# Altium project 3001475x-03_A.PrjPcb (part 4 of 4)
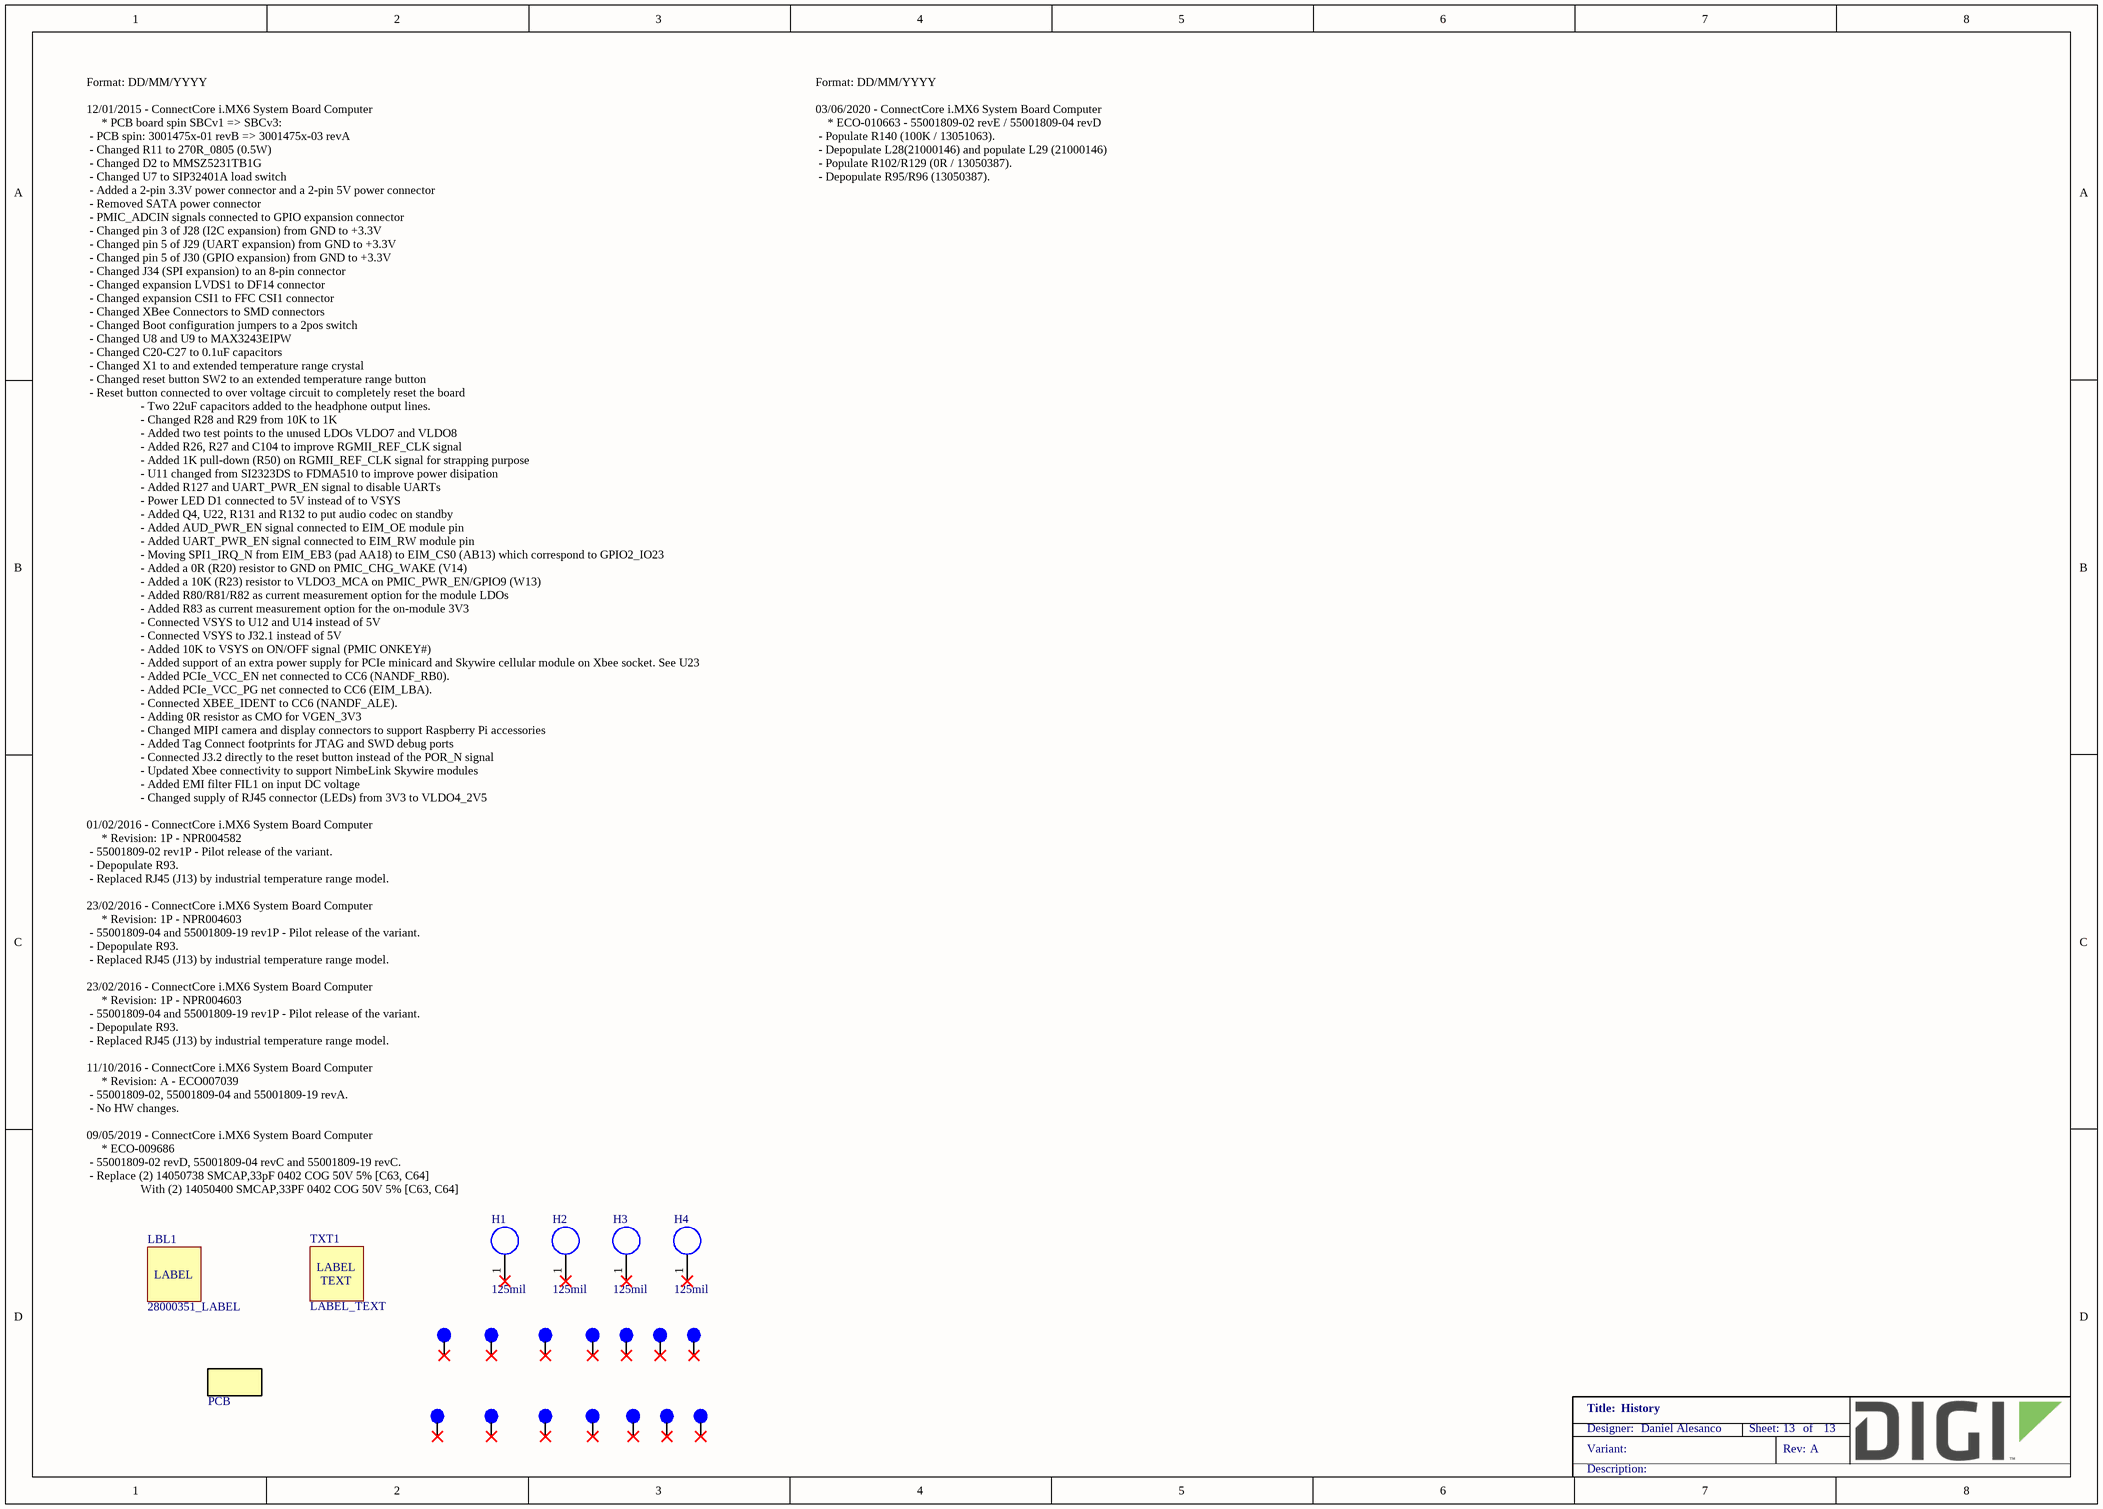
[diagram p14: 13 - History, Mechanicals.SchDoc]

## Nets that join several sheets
3V3: 02 - CCIMX6 Module (R83.1 U1.P5 U1.Y9 U1.Y13), 03 - Power, boot strap, reset (14 pins), 04 - SATA, microSD, Mini PCIe, microSIM (9 pins), 05 - JTAG, SWD, Console, UART (13 pins), 06 - Gigabit Ethernet (L2.1 U11.4 U11.8), 07 - USB OTG, USB HUB, USB Host (8 pins), 08 - Displays, HDMI, Cameras (19 pins), 09 - Audio (R93.2 R128.1 R132.2 U22.S), 10 - CAN, I2C, XBee (8 pins), 11 - Expansion Connectors, User LEDs (6 pins)
5V: 02 - CCIMX6 Module (U1.F16), 03 - Power, boot strap, reset (J5.1 R12.2 R21.2), 08 - Displays, HDMI, Cameras (7 pins)
GND: 02 - CCIMX6 Module (61 pins), 03 - Power, boot strap, reset (37 pins), 04 - SATA, microSD, Mini PCIe, microSIM (52 pins), 05 - JTAG, SWD, Console, UART (17 pins), 06 - Gigabit Ethernet (38 pins), 07 - USB OTG, USB HUB, USB Host (38 pins), 08 - Displays, HDMI, Cameras (53 pins), 09 - Audio (12 pins), 10 - CAN, I2C, XBee (15 pins), 11 - Expansion Connectors, User LEDs (12 pins)
PCIe_VCC: 04 - SATA, microSD, Mini PCIe, microSIM (18 pins), 10 - CAN, I2C, XBee (L29.1)
SHLD: 04 - SATA, microSD, Mini PCIe, microSIM (J7.11 J7.12), 06 - Gigabit Ethernet (C33.1 J13.SHLD1 J13.SHLD2 R46.2), 07 - USB OTG, USB HUB, USB Host (8 pins), 08 - Displays, HDMI, Cameras (P1.M1 P1.M2 P1.M3 P1.M4)
VCC_LICELL: 02 - CCIMX6 Module (U1.N3), 03 - Power, boot strap, reset (R8.2)
VLDO3_MCA: 02 - CCIMX6 Module (R23.2 R80.1 R153.2 U1.AC10), 05 - JTAG, SWD, Console, UART (CAD2.1 J11.1 R150.1)
VLDO4_2V5: 02 - CCIMX6 Module (R81.1 U1.R5 U1.V3), 06 - Gigabit Ethernet (14 pins)
VLDO6_1V5: 02 - CCIMX6 Module (R82.1), 04 - SATA, microSD, Mini PCIe, microSIM (5 pins), 09 - Audio (R131.2)
VSYS: 02 - CCIMX6 Module (U1.V11 U1.W11 U1.W12), 03 - Power, boot strap, reset (8 pins), 04 - SATA, microSD, Mini PCIe, microSIM (7 pins), 05 - JTAG, SWD, Console, UART (R151.1 R152.1), 07 - USB OTG, USB HUB, USB Host (C62.2 C65.1 U12.7 U14.7), 08 - Displays, HDMI, Cameras (J18.1), 10 - CAN, I2C, XBee (R101.1), 11 - Expansion Connectors, User LEDs (J32.1)
AUD_CLK: 02 - CCIMX6 Module (R1.2), 09 - Audio (U17.21)
AUD_HP_DET: 02 - CCIMX6 Module (U1.J24), 09 - Audio (D9.2 J22.5 R93.1)
AUD_I2C_SCL: 09 - Audio (U17.29), 10 - CAN, I2C, XBee (R114.2)
AUD_I2C_SDA: 09 - Audio (U17.27), 10 - CAN, I2C, XBee (R115.2)
AUD_PWR_EN: 02 - CCIMX6 Module (U1.V15), 09 - Audio (Q4.G R132.1)
AUD_RXD: 02 - CCIMX6 Module (U1.M5), 09 - Audio (U17.25)
AUD_TXC: 02 - CCIMX6 Module (U1.B7), 09 - Audio (U17.24)
AUD_TXD: 02 - CCIMX6 Module (U1.C7), 09 - Audio (U17.26)
AUD_TXFS: 02 - CCIMX6 Module (U1.C5), 09 - Audio (U17.23)
BOOT_CFG_1_4: 02 - CCIMX6 Module (U1.W24), 03 - Power, boot strap, reset (R18.1)
BOOT_CFG_1_5: 02 - CCIMX6 Module (U1.AA19), 03 - Power, boot strap, reset (R10.1 SW3.3 U4.1)
BOOT_CFG_1_6: 02 - CCIMX6 Module (U1.U23), 03 - Power, boot strap, reset (R9.1 SW3.4 U2.1)
BOOT_CFG_1_7: 02 - CCIMX6 Module (U1.Y21), 03 - Power, boot strap, reset (R19.1)
BOOT_CFG_2_5: 02 - CCIMX6 Module (U1.V20), 03 - Power, boot strap, reset (R16.1)
BOOT_CFG_2_6: 02 - CCIMX6 Module (U1.W21), 03 - Power, boot strap, reset (R17.1)
BOOT_MODE0: 02 - CCIMX6 Module (U1.E17), 03 - Power, boot strap, reset (R24.1 R28.1)
BOOT_MODE1: 02 - CCIMX6 Module (U1.F15), 03 - Power, boot strap, reset (R25.1 R29.1)
CAN1_H: 10 - CAN, I2C, XBee (R104.2 U18.7), 11 - Expansion Connectors, User LEDs (J27.2)
CAN1_L: 10 - CAN, I2C, XBee (R104.1 U18.6), 11 - Expansion Connectors, User LEDs (J27.1)
CAN1_RXD: 02 - CCIMX6 Module (U1.F3), 10 - CAN, I2C, XBee (U18.4)
CAN1_STBY: 02 - CCIMX6 Module (U1.G3), 10 - CAN, I2C, XBee (U18.8)
CAN1_TXD: 02 - CCIMX6 Module (U1.P3), 10 - CAN, I2C, XBee (U18.1)
CAN2_H: 10 - CAN, I2C, XBee (R116.2 U19.7), 11 - Expansion Connectors, User LEDs (J27.5)
CAN2_L: 10 - CAN, I2C, XBee (R116.1 U19.6), 11 - Expansion Connectors, User LEDs (J27.4)
CAN2_RXD: 02 - CCIMX6 Module (U1.D21), 10 - CAN, I2C, XBee (U19.4)
CAN2_STBY: 02 - CCIMX6 Module (U1.R3), 10 - CAN, I2C, XBee (U19.8)
CAN2_TXD: 02 - CCIMX6 Module (U1.F20), 10 - CAN, I2C, XBee (U19.1)
CLK1_N: 02 - CCIMX6 Module (U1.B18), 04 - SATA, microSD, Mini PCIe, microSIM (C31.1)
CLK1_P: 02 - CCIMX6 Module (U1.A18), 04 - SATA, microSD, Mini PCIe, microSIM (C32.1)
CSI0_DAT12: 02 - CCIMX6 Module (U1.L5), 08 - Displays, HDMI, Cameras (J17.2)
CSI0_DAT13: 02 - CCIMX6 Module (U1.C6), 08 - Displays, HDMI, Cameras (J17.3)
CSI0_DAT14: 02 - CCIMX6 Module (U1.B6), 08 - Displays, HDMI, Cameras (J17.4)
CSI0_DAT15: 02 - CCIMX6 Module (U1.E6), 08 - Displays, HDMI, Cameras (J17.5)
CSI0_DAT16: 02 - CCIMX6 Module (U1.H6), 08 - Displays, HDMI, Cameras (J17.6)
CSI0_DAT17: 02 - CCIMX6 Module (U1.A7), 08 - Displays, HDMI, Cameras (J17.7)
CSI0_DAT18: 02 - CCIMX6 Module (U1.F6), 08 - Displays, HDMI, Cameras (J17.8)
CSI0_DAT19: 02 - CCIMX6 Module (U1.G6), 08 - Displays, HDMI, Cameras (J17.9)
CSI0_GPIO: 02 - CCIMX6 Module (U1.E5), 08 - Displays, HDMI, Cameras (J17.15)
CSI0_HSYNC: 02 - CCIMX6 Module (U1.A5), 08 - Displays, HDMI, Cameras (J17.13)
CSI0_I2C_SCL: 08 - Displays, HDMI, Cameras (J17.18), 10 - CAN, I2C, XBee (R108.2)
CSI0_I2C_SDA: 08 - Displays, HDMI, Cameras (J17.19), 10 - CAN, I2C, XBee (R111.2)
CSI0_MCLK: 02 - CCIMX6 Module (R3.2), 08 - Displays, HDMI, Cameras (J17.11)
CSI0_PIXCLK: 02 - CCIMX6 Module (U1.G5), 08 - Displays, HDMI, Cameras (J17.12)
CSI0_RESET_N: 02 - CCIMX6 Module (U1.AA13), 08 - Displays, HDMI, Cameras (J17.16)
CSI0_VSYNC: 02 - CCIMX6 Module (U1.J5), 08 - Displays, HDMI, Cameras (J17.14)
CSI1_DAT12: 02 - CCIMX6 Module (U1.AC17), 08 - Displays, HDMI, Cameras (J33.2)
CSI1_DAT13: 02 - CCIMX6 Module (U1.AB15), 08 - Displays, HDMI, Cameras (J33.3)
CSI1_DAT14: 02 - CCIMX6 Module (U1.AD16), 08 - Displays, HDMI, Cameras (J33.4)
CSI1_DAT15: 02 - CCIMX6 Module (U1.AB16), 08 - Displays, HDMI, Cameras (J33.5)
CSI1_DAT16: 02 - CCIMX6 Module (U1.AC16), 08 - Displays, HDMI, Cameras (J33.6)
CSI1_DAT17: 02 - CCIMX6 Module (U1.AC19), 08 - Displays, HDMI, Cameras (J33.7)
CSI1_DAT18: 02 - CCIMX6 Module (U1.AA14), 08 - Displays, HDMI, Cameras (J33.8)
CSI1_DAT19: 02 - CCIMX6 Module (U1.AD17), 08 - Displays, HDMI, Cameras (J33.9)
CSI1_GPIO: 02 - CCIMX6 Module (U1.W18), 08 - Displays, HDMI, Cameras (J33.15)
CSI1_HSYNC: 03 - Power, boot strap, reset (U2.3), 08 - Displays, HDMI, Cameras (J33.13)
CSI1_HSYNC/BTCFG2_3: 02 - CCIMX6 Module (U1.V18), 03 - Power, boot strap, reset (U2.4)
CSI1_I2C_SCL: 08 - Displays, HDMI, Cameras (J33.18), 10 - CAN, I2C, XBee (R207.2)
CSI1_I2C_SDA: 08 - Displays, HDMI, Cameras (J33.19), 10 - CAN, I2C, XBee (R208.2)
CSI1_MCLK: 02 - CCIMX6 Module (R2.2), 08 - Displays, HDMI, Cameras (J33.11)
CSI1_PIXCLK: 02 - CCIMX6 Module (U1.AD15), 08 - Displays, HDMI, Cameras (J33.12)
CSI1_RESET_N: 02 - CCIMX6 Module (U1.Y20), 08 - Displays, HDMI, Cameras (J33.16)
CSI1_VSYNC: 03 - Power, boot strap, reset (U4.3), 08 - Displays, HDMI, Cameras (J33.14)
CSI1_VSYNC/BTCFG2_4: 02 - CCIMX6 Module (U1.V22), 03 - Power, boot strap, reset (U4.4)
CSI_CLK0_N: 02 - CCIMX6 Module (U1.B11), 08 - Displays, HDMI, Cameras (P20.8)
CSI_CLK0_P: 02 - CCIMX6 Module (U1.A11), 08 - Displays, HDMI, Cameras (P20.7)
CSI_D0_N: 02 - CCIMX6 Module (U1.G12), 08 - Displays, HDMI, Cameras (P20.14)
CSI_D0_P: 02 - CCIMX6 Module (U1.G11), 08 - Displays, HDMI, Cameras (P20.13)
CSI_D1_N: 02 - CCIMX6 Module (U1.A13), 08 - Displays, HDMI, Cameras (P20.11)
CSI_D1_P: 02 - CCIMX6 Module (U1.B13), 08 - Displays, HDMI, Cameras (P20.10)
CSI_I2C_SCL: 08 - Displays, HDMI, Cameras (P20.3), 10 - CAN, I2C, XBee (R112.2)
CSI_I2C_SDA: 08 - Displays, HDMI, Cameras (P20.2), 10 - CAN, I2C, XBee (R113.2)
CSI_RESET_N: 02 - CCIMX6 Module (U1.E24), 08 - Displays, HDMI, Cameras (P20.5)
DISP0_CLK: 02 - CCIMX6 Module (U1.V9), 08 - Displays, HDMI, Cameras (J21.27)
DISP0_CONTRAST: 02 - CCIMX6 Module (U1.AD8), 08 - Displays, HDMI, Cameras (J21.32)
DISP0_DAT0: 02 - CCIMX6 Module (U1.AC8), 08 - Displays, HDMI, Cameras (J21.2)
DISP0_DAT1: 02 - CCIMX6 Module (U1.AC9), 08 - Displays, HDMI, Cameras (J21.3)
DISP0_DAT2: 02 - CCIMX6 Module (U1.AD9), 08 - Displays, HDMI, Cameras (J21.4)
DISP0_DAT3: 02 - CCIMX6 Module (U1.AB8), 08 - Displays, HDMI, Cameras (J21.5)
DISP0_DAT4: 02 - CCIMX6 Module (U1.AA9), 08 - Displays, HDMI, Cameras (J21.6)
DISP0_DAT5: 02 - CCIMX6 Module (U1.AD7), 08 - Displays, HDMI, Cameras (J21.7)
DISP0_DAT6: 02 - CCIMX6 Module (U1.AB7), 08 - Displays, HDMI, Cameras (J21.8)
DISP0_DAT7: 02 - CCIMX6 Module (U1.AC7), 08 - Displays, HDMI, Cameras (J21.9)
DISP0_DAT8: 02 - CCIMX6 Module (U1.AA8), 08 - Displays, HDMI, Cameras (J21.10)
DISP0_DAT9: 02 - CCIMX6 Module (U1.AB6), 08 - Displays, HDMI, Cameras (J21.11)
DISP0_DAT10: 02 - CCIMX6 Module (U1.Y8), 08 - Displays, HDMI, Cameras (J21.12)
DISP0_DAT11: 02 - CCIMX6 Module (U1.Y7), 08 - Displays, HDMI, Cameras (J21.13)
DISP0_DAT12: 02 - CCIMX6 Module (U1.AA7), 08 - Displays, HDMI, Cameras (J21.14)
DISP0_DAT13: 02 - CCIMX6 Module (U1.W8), 08 - Displays, HDMI, Cameras (J21.15)
DISP0_DAT14: 02 - CCIMX6 Module (U1.AC6), 08 - Displays, HDMI, Cameras (J21.16)
DISP0_DAT15: 02 - CCIMX6 Module (U1.W7), 08 - Displays, HDMI, Cameras (J21.17)
DISP0_DAT16: 02 - CCIMX6 Module (U1.V6), 08 - Displays, HDMI, Cameras (J21.18)
DISP0_DAT17: 02 - CCIMX6 Module (U1.AB5), 08 - Displays, HDMI, Cameras (J21.19)
DISP0_DAT18: 02 - CCIMX6 Module (U1.AD6), 08 - Displays, HDMI, Cameras (J21.20)
DISP0_DAT19: 02 - CCIMX6 Module (U1.Y6), 08 - Displays, HDMI, Cameras (J21.21)
DISP0_DAT20: 02 - CCIMX6 Module (U1.W6), 08 - Displays, HDMI, Cameras (J21.22)
DISP0_DAT21: 02 - CCIMX6 Module (U1.U6), 08 - Displays, HDMI, Cameras (J21.23)
DISP0_DAT22: 02 - CCIMX6 Module (U1.V7), 08 - Displays, HDMI, Cameras (J21.24)
DISP0_DAT23: 02 - CCIMX6 Module (U1.AA6), 08 - Displays, HDMI, Cameras (J21.25)
DISP0_DRDY: 02 - CCIMX6 Module (U1.V10), 08 - Displays, HDMI, Cameras (J21.31)
DISP0_HSYNC: 02 - CCIMX6 Module (U1.W10), 08 - Displays, HDMI, Cameras (J21.29)
DISP0_I2C_SCL: 08 - Displays, HDMI, Cameras (J21.33), 10 - CAN, I2C, XBee (R103.2)
DISP0_I2C_SDA: 08 - Displays, HDMI, Cameras (J21.34), 10 - CAN, I2C, XBee (R105.2)
DISP0_IRQ_N: 02 - CCIMX6 Module (U1.H22), 08 - Displays, HDMI, Cameras (J21.35 R78.2)
DISP0_VSYNC: 02 - CCIMX6 Module (U1.V8), 08 - Displays, HDMI, Cameras (J21.30)
DSI_CLK0_N: 02 - CCIMX6 Module (U1.E10), 08 - Displays, HDMI, Cameras (P18.11)
DSI_CLK0_P: 02 - CCIMX6 Module (U1.F10), 08 - Displays, HDMI, Cameras (P18.10)
DSI_D0_N: 02 - CCIMX6 Module (U1.C10), 08 - Displays, HDMI, Cameras (P18.8)
DSI_D0_P: 02 - CCIMX6 Module (U1.B10), 08 - Displays, HDMI, Cameras (P18.7)
DSI_D1_N: 02 - CCIMX6 Module (U1.E9), 08 - Displays, HDMI, Cameras (P18.14)
DSI_D1_P: 02 - CCIMX6 Module (U1.D9), 08 - Displays, HDMI, Cameras (P18.13)
DSI_I2C_SCL: 08 - Displays, HDMI, Cameras (P18.5), 10 - CAN, I2C, XBee (R155.2)
DSI_I2C_SDA: 08 - Displays, HDMI, Cameras (P18.4), 10 - CAN, I2C, XBee (R156.2)
EXP_GPIO_0: 02 - CCIMX6 Module (U1.L24), 11 - Expansion Connectors, User LEDs (J30.6)
EXP_GPIO_1: 02 - CCIMX6 Module (U1.G22), 11 - Expansion Connectors, User LEDs (J30.7)
EXP_GPIO_2: 02 - CCIMX6 Module (U1.H23), 11 - Expansion Connectors, User LEDs (J30.8)
EXP_GPIO_3: 02 - CCIMX6 Module (U1.AC15), 11 - Expansion Connectors, User LEDs (J30.9)
EXP_GPIO_4: 02 - CCIMX6 Module (U1.Y14), 11 - Expansion Connectors, User LEDs (J30.10)
EXP_GPIO_5: 02 - CCIMX6 Module (U1.V16), 11 - Expansion Connectors, User LEDs (J30.11)
EXP_GPIO_6: 02 - CCIMX6 Module (U1.N2), 11 - Expansion Connectors, User LEDs (J30.12)
EXP_GPIO_7: 02 - CCIMX6 Module (U1.M2), 11 - Expansion Connectors, User LEDs (J30.13)
EXP_I2C_GPIO: 02 - CCIMX6 Module (U1.F23), 11 - Expansion Connectors, User LEDs (J28.5)
EXP_I2C_IRQ_N: 02 - CCIMX6 Module (U1.H24), 11 - Expansion Connectors, User LEDs (J28.4 R117.2)
EXP_I2C_SCL: 10 - CAN, I2C, XBee (R106.2), 11 - Expansion Connectors, User LEDs (J28.1)
EXP_I2C_SDA: 10 - CAN, I2C, XBee (R107.2), 11 - Expansion Connectors, User LEDs (J28.2)
HDMI_CEC_IN: 02 - CCIMX6 Module (U1.H2), 08 - Displays, HDMI, Cameras (R88.2 U16.16)
HDMI_CLK_N: 02 - CCIMX6 Module (U1.E8), 08 - Displays, HDMI, Cameras (L43.4)
HDMI_CLK_P: 02 - CCIMX6 Module (U1.F8), 08 - Displays, HDMI, Cameras (L43.1)
HDMI_D0_N: 02 - CCIMX6 Module (U1.A9), 08 - Displays, HDMI, Cameras (L41.4)
HDMI_D0_P: 02 - CCIMX6 Module (U1.B9), 08 - Displays, HDMI, Cameras (L41.1)
HDMI_D1_N: 02 - CCIMX6 Module (U1.B8), 08 - Displays, HDMI, Cameras (L39.4)
HDMI_D1_P: 02 - CCIMX6 Module (U1.C8), 08 - Displays, HDMI, Cameras (L39.1)
HDMI_D2_N: 02 - CCIMX6 Module (U1.F7), 08 - Displays, HDMI, Cameras (L37.4)
HDMI_D2_P: 02 - CCIMX6 Module (U1.G7), 08 - Displays, HDMI, Cameras (L37.1)
HDMI_HPD: 02 - CCIMX6 Module (U1.G9), 08 - Displays, HDMI, Cameras (C83.2 R90.2 U16.19)
HDMI_I2C_SCL: 08 - Displays, HDMI, Cameras (U16.17), 10 - CAN, I2C, XBee (R99.2)
HDMI_I2C_SDA: 08 - Displays, HDMI, Cameras (U16.18), 10 - CAN, I2C, XBee (R100.2)
I2C3_SCL: 02 - CCIMX6 Module (U1.T3), 10 - CAN, I2C, XBee (12 pins)
I2C3_SDA: 02 - CCIMX6 Module (U1.J3), 10 - CAN, I2C, XBee (12 pins)
JTAG_MOD: 02 - CCIMX6 Module (U1.G13), 05 - JTAG, SWD, Console, UART (R37.2)
JTAG_TCK: 02 - CCIMX6 Module (U1.F13), 05 - JTAG, SWD, Console, UART (CAD1.4 J10.4)
JTAG_TDI: 02 - CCIMX6 Module (U1.D14), 05 - JTAG, SWD, Console, UART (CAD1.8 J10.8)
JTAG_TDO: 02 - CCIMX6 Module (U1.E14), 05 - JTAG, SWD, Console, UART (CAD1.6 J10.6)
JTAG_TMS: 02 - CCIMX6 Module (U1.F14), 05 - JTAG, SWD, Console, UART (CAD1.2 J10.2)
JTAG_TRST_N: 02 - CCIMX6 Module (U1.D15), 05 - JTAG, SWD, Console, UART (CAD1.9 R36.1)
LINE_IN_L: 09 - Audio (L21.1), 11 - Expansion Connectors, User LEDs (J26.4)
LINE_IN_R: 09 - Audio (L20.1), 11 - Expansion Connectors, User LEDs (J26.3)
LINE_OUT_L: 09 - Audio (L19.2), 11 - Expansion Connectors, User LEDs (J26.7)
LINE_OUT_R: 09 - Audio (L18.2), 11 - Expansion Connectors, User LEDs (J26.6)
LVDS0_CLK_N: 02 - CCIMX6 Module (U1.M4), 08 - Displays, HDMI, Cameras (L33.1)
LVDS0_CLK_P: 02 - CCIMX6 Module (U1.L4), 08 - Displays, HDMI, Cameras (L33.4)
LVDS0_CONTRAST: 02 - CCIMX6 Module (U1.V12), 08 - Displays, HDMI, Cameras (J19.16)
LVDS0_I2C_SCL: 08 - Displays, HDMI, Cameras (J19.17), 10 - CAN, I2C, XBee (R97.2)
LVDS0_I2C_SDA: 08 - Displays, HDMI, Cameras (J19.18), 10 - CAN, I2C, XBee (R98.2)
LVDS0_IRQ_N: 02 - CCIMX6 Module (U1.M3), 08 - Displays, HDMI, Cameras (J19.19 R76.2)
LVDS0_TX0_N: 02 - CCIMX6 Module (U1.J4), 08 - Displays, HDMI, Cameras (L30.1)
LVDS0_TX0_P: 02 - CCIMX6 Module (U1.H4), 08 - Displays, HDMI, Cameras (L30.4)
LVDS0_TX1_N: 02 - CCIMX6 Module (U1.F4), 08 - Displays, HDMI, Cameras (L31.1)
LVDS0_TX1_P: 02 - CCIMX6 Module (U1.E4), 08 - Displays, HDMI, Cameras (L31.4)
LVDS0_TX2_N: 02 - CCIMX6 Module (U1.C4), 08 - Displays, HDMI, Cameras (L32.1)
LVDS0_TX2_P: 02 - CCIMX6 Module (U1.B4), 08 - Displays, HDMI, Cameras (L32.4)
LVDS0_TX3_N: 02 - CCIMX6 Module (U1.R4), 08 - Displays, HDMI, Cameras (L34.1)
LVDS0_TX3_P: 02 - CCIMX6 Module (U1.P4), 08 - Displays, HDMI, Cameras (L34.4)
LVDS1_CLK_N: 02 - CCIMX6 Module (U1.E1), 08 - Displays, HDMI, Cameras (L42.1)
LVDS1_CLK_P: 02 - CCIMX6 Module (U1.F1), 08 - Displays, HDMI, Cameras (L42.4)
LVDS1_CONTRAST: 02 - CCIMX6 Module (U1.V13), 08 - Displays, HDMI, Cameras (J31.16)
LVDS1_I2C_SCL: 08 - Displays, HDMI, Cameras (J31.17), 10 - CAN, I2C, XBee (R298.2)
LVDS1_I2C_SDA: 08 - Displays, HDMI, Cameras (J31.18), 10 - CAN, I2C, XBee (R299.2)
LVDS1_IRQ_N: 02 - CCIMX6 Module (U1.AC20), 08 - Displays, HDMI, Cameras (J31.19 R118.2)
LVDS1_TX0_N: 02 - CCIMX6 Module (U1.H1), 08 - Displays, HDMI, Cameras (L36.1)
LVDS1_TX0_P: 02 - CCIMX6 Module (U1.J1), 08 - Displays, HDMI, Cameras (L36.4)
LVDS1_TX1_N: 02 - CCIMX6 Module (U1.M1), 08 - Displays, HDMI, Cameras (L38.1)
LVDS1_TX1_P: 02 - CCIMX6 Module (U1.L1), 08 - Displays, HDMI, Cameras (L38.4)
LVDS1_TX2_N: 02 - CCIMX6 Module (U1.P1), 08 - Displays, HDMI, Cameras (L40.1)
LVDS1_TX2_P: 02 - CCIMX6 Module (U1.R1), 08 - Displays, HDMI, Cameras (L40.4)
LVDS1_TX3_N: 02 - CCIMX6 Module (U1.U1), 08 - Displays, HDMI, Cameras (L44.1)
LVDS1_TX3_P: 02 - CCIMX6 Module (U1.V1), 08 - Displays, HDMI, Cameras (L44.4)
MCA_RESET_N: 02 - CCIMX6 Module (U1.N23), 05 - JTAG, SWD, Console, UART (CAD2.10 J11.10)
MCA_SWD_CLK: 02 - CCIMX6 Module (U1.L23), 05 - JTAG, SWD, Console, UART (CAD2.4 J11.4)
MCA_SWD_DIO: 02 - CCIMX6 Module (U1.M23), 05 - JTAG, SWD, Console, UART (CAD2.2 J11.2)
MIC_BIAS: 09 - Audio (L23.1), 11 - Expansion Connectors, User LEDs (J26.1)
MIC_IN: 09 - Audio (L22.1), 11 - Expansion Connectors, User LEDs (J26.2)
ON/OFF: 02 - CCIMX6 Module (U1.D18), 03 - Power, boot strap, reset (J3.1 R147.1 SW1.3 SW1.4)
PCIE_DIS_N: 02 - CCIMX6 Module (U1.L3), 04 - SATA, microSD, Mini PCIe, microSIM (J12.20)
PCIE_I2C_SCL: 04 - SATA, microSD, Mini PCIe, microSIM (J12.30), 10 - CAN, I2C, XBee (R95.2)
PCIE_I2C_SDA: 04 - SATA, microSD, Mini PCIe, microSIM (J12.32), 10 - CAN, I2C, XBee (R96.2)
PCIE_RESET_N: 02 - CCIMX6 Module (U1.D22), 04 - SATA, microSD, Mini PCIe, microSIM (J12.22)
PCIE_RX_N: 02 - CCIMX6 Module (U1.A14), 04 - SATA, microSD, Mini PCIe, microSIM (R44.1)
PCIE_RX_P: 02 - CCIMX6 Module (U1.B14), 04 - SATA, microSD, Mini PCIe, microSIM (R47.1)
PCIE_TX_N: 02 - CCIMX6 Module (U1.A15), 04 - SATA, microSD, Mini PCIe, microSIM (R51.1)
PCIE_TX_P: 02 - CCIMX6 Module (U1.B15), 04 - SATA, microSD, Mini PCIe, microSIM (R52.1)
PCIe_VCC_EN: 02 - CCIMX6 Module (U1.M24), 04 - SATA, microSD, Mini PCIe, microSIM (R141.1)
PCIe_VCC_PG: 02 - CCIMX6 Module (U1.U21), 04 - SATA, microSD, Mini PCIe, microSIM (R139.2 U23.5)
PCIE_WAKE_N: 02 - CCIMX6 Module (U1.F24), 04 - SATA, microSD, Mini PCIe, microSIM (J12.1)
PMIC_ADCIN1: 02 - CCIMX6 Module (U1.AB14), 11 - Expansion Connectors, User LEDs (R204.1)
PMIC_ADCIN2: 02 - CCIMX6 Module (U1.AC14), 11 - Expansion Connectors, User LEDs (R205.1)
PMIC_ADCIN3: 02 - CCIMX6 Module (U1.AD14), 11 - Expansion Connectors, User LEDs (R206.1)
POR_N: 02 - CCIMX6 Module (U1.E18), 03 - Power, boot strap, reset (R7.1 R15.1 R123.2), 05 - JTAG, SWD, Console, UART (CAD1.10 J10.10)
PWR_EN: 02 - CCIMX6 Module (U1.AB9), 03 - Power, boot strap, reset (R22.1 U7.4)
RGMII_INT_N: 02 - CCIMX6 Module (U1.AA3), 06 - Gigabit Ethernet (R40.1 U10.38)
RGMII_MDC: 02 - CCIMX6 Module (U1.W3), 06 - Gigabit Ethernet (U10.36)
RGMII_MDIO: 02 - CCIMX6 Module (U1.Y3), 06 - Gigabit Ethernet (R41.1 U10.37)
RGMII_RD0: 02 - CCIMX6 Module (U1.AA4), 06 - Gigabit Ethernet (R60.1 U10.32)
RGMII_RD1: 02 - CCIMX6 Module (U1.AB3), 06 - Gigabit Ethernet (R61.1 U10.31)
RGMII_RD2: 02 - CCIMX6 Module (U1.AC4), 06 - Gigabit Ethernet (R62.1 U10.28)
RGMII_RD3: 02 - CCIMX6 Module (U1.AC5), 06 - Gigabit Ethernet (R63.1 U10.27)
RGMII_REF_CLK: 02 - CCIMX6 Module (U1.Y1), 06 - Gigabit Ethernet (C104.1 R26.1 R27.2)
RGMII_RESET_N: 02 - CCIMX6 Module (U1.P2), 06 - Gigabit Ethernet (U10.42)
RGMII_RX_CTL: 02 - CCIMX6 Module (U1.V4), 06 - Gigabit Ethernet (R58.1 R59.1 U10.33)
RGMII_RXC: 02 - CCIMX6 Module (U1.AD5), 06 - Gigabit Ethernet (R57.1 U10.35)
RGMII_TD0: 02 - CCIMX6 Module (U1.U5), 06 - Gigabit Ethernet (U10.19)
RGMII_TD1: 02 - CCIMX6 Module (U1.V5), 06 - Gigabit Ethernet (U10.20)
RGMII_TD2: 02 - CCIMX6 Module (U1.Y5), 06 - Gigabit Ethernet (U10.21)
RGMII_TD3: 02 - CCIMX6 Module (U1.AA5), 06 - Gigabit Ethernet (U10.22)
RGMII_TX_CTL: 02 - CCIMX6 Module (U1.W4), 06 - Gigabit Ethernet (U10.25)
RGMII_TXC: 02 - CCIMX6 Module (U1.U4), 06 - Gigabit Ethernet (U10.24)
RS232_1_CTS_N: 05 - JTAG, SWD, Console, UART (U8.6), 11 - Expansion Connectors, User LEDs (J29.4)
RS232_1_RTS_N: 05 - JTAG, SWD, Console, UART (U8.11), 11 - Expansion Connectors, User LEDs (J29.3)
RS232_1_RX: 05 - JTAG, SWD, Console, UART (U8.5), 11 - Expansion Connectors, User LEDs (J29.2)
RS232_1_TX: 05 - JTAG, SWD, Console, UART (U8.10), 11 - Expansion Connectors, User LEDs (J29.1)
RS232_3_CTS_N: 05 - JTAG, SWD, Console, UART (U9.5), 11 - Expansion Connectors, User LEDs (J29.9)
RS232_3_RTS_N: 05 - JTAG, SWD, Console, UART (U9.10), 11 - Expansion Connectors, User LEDs (J29.8)
RS232_3_RX: 05 - JTAG, SWD, Console, UART (U9.4), 11 - Expansion Connectors, User LEDs (J29.7)
RS232_3_TX: 05 - JTAG, SWD, Console, UART (U9.9), 11 - Expansion Connectors, User LEDs (J29.6)
SATA_RX_N: 02 - CCIMX6 Module (U1.G19), 04 - SATA, microSD, Mini PCIe, microSIM (C16.1)
SATA_RX_P: 02 - CCIMX6 Module (U1.H19), 04 - SATA, microSD, Mini PCIe, microSIM (C17.1)
SATA_TX_N: 02 - CCIMX6 Module (U1.D19), 04 - SATA, microSD, Mini PCIe, microSIM (C15.1)
SATA_TX_P: 02 - CCIMX6 Module (U1.E19), 04 - SATA, microSD, Mini PCIe, microSIM (C14.1)
SD2_CLK: 02 - CCIMX6 Module (U1.K22), 04 - SATA, microSD, Mini PCIe, microSIM (R35.1)
SD2_CMD: 02 - CCIMX6 Module (U1.M20), 04 - SATA, microSD, Mini PCIe, microSIM (J7.3 R30.1)
SD2_DAT0: 02 - CCIMX6 Module (U1.P24), 04 - SATA, microSD, Mini PCIe, microSIM (J7.7 R34.1)
SD2_DAT1: 02 - CCIMX6 Module (U1.K21), 04 - SATA, microSD, Mini PCIe, microSIM (J7.8 R33.1)
SD2_DAT2: 02 - CCIMX6 Module (U1.R24), 04 - SATA, microSD, Mini PCIe, microSIM (J7.1 R32.1)
SD2_DAT3: 02 - CCIMX6 Module (U1.K23), 04 - SATA, microSD, Mini PCIe, microSIM (J7.2 R31.1)
SPI1_CLK: 02 - CCIMX6 Module (U1.AD20), 11 - Expansion Connectors, User LEDs (J34.2)
SPI1_IRQ_N: 02 - CCIMX6 Module (U1.AB13), 11 - Expansion Connectors, User LEDs (J34.7 R122.2)
SPI1_MISO: 02 - CCIMX6 Module (U1.V17), 11 - Expansion Connectors, User LEDs (J34.3)
SPI1_MOSI: 02 - CCIMX6 Module (U1.AB18), 11 - Expansion Connectors, User LEDs (J34.4)
SPI1_SS0: 02 - CCIMX6 Module (U1.Y24), 11 - Expansion Connectors, User LEDs (J34.5)
SPI1_SS1: 02 - CCIMX6 Module (U1.K2), 11 - Expansion Connectors, User LEDs (J34.6)
TOUCH_X1: 02 - CCIMX6 Module (U1.T23), 11 - Expansion Connectors, User LEDs (R257.1)
TOUCH_X2: 02 - CCIMX6 Module (U1.R23), 11 - Expansion Connectors, User LEDs (R258.1)
TOUCH_Y1: 02 - CCIMX6 Module (U1.U24), 11 - Expansion Connectors, User LEDs (R259.1)
TOUCH_Y2: 02 - CCIMX6 Module (U1.R22), 11 - Expansion Connectors, User LEDs (J30.4)
UART1_CTS_N: 02 - CCIMX6 Module (U1.Y17), 05 - JTAG, SWD, Console, UART (U8.12)
UART1_RTS_N: 02 - CCIMX6 Module (U1.W19), 05 - JTAG, SWD, Console, UART (U8.17)
UART1_RX: 02 - CCIMX6 Module (U1.E21), 05 - JTAG, SWD, Console, UART (U8.18)
UART1_TX: 02 - CCIMX6 Module (U1.C21), 05 - JTAG, SWD, Console, UART (U8.13)
UART3_CTS_N: 02 - CCIMX6 Module (U1.Y15), 05 - JTAG, SWD, Console, UART (U9.13)
UART3_RTS_N: 02 - CCIMX6 Module (U1.AA15), 05 - JTAG, SWD, Console, UART (U9.18)
UART3_RX: 02 - CCIMX6 Module (U1.AA17), 05 - JTAG, SWD, Console, UART (U9.19)
UART3_TX: 02 - CCIMX6 Module (U1.W20), 05 - JTAG, SWD, Console, UART (U9.14)
UART4_RX: 02 - CCIMX6 Module (U1.E2), 05 - JTAG, SWD, Console, UART (U8.19)
UART4_TX: 02 - CCIMX6 Module (U1.J2), 05 - JTAG, SWD, Console, UART (U8.14)
UART5_CTS_N: 02 - CCIMX6 Module (U1.D2), 10 - CAN, I2C, XBee (J24.5 R145.2), 11 - Expansion Connectors, User LEDs (J29.14)
UART5_RTS_N: 02 - CCIMX6 Module (U1.L2), 10 - CAN, I2C, XBee (J24.9), 11 - Expansion Connectors, User LEDs (J29.13)
UART5_RX: 02 - CCIMX6 Module (U1.D3), 10 - CAN, I2C, XBee (J23.2), 11 - Expansion Connectors, User LEDs (J29.12)
UART5_TX: 02 - CCIMX6 Module (U1.E3), 10 - CAN, I2C, XBee (J23.3), 11 - Expansion Connectors, User LEDs (J29.11)
UART_PWR_EN: 02 - CCIMX6 Module (U1.W15), 05 - JTAG, SWD, Console, UART (R127.2 U8.22 U9.22)
USB_HUB_RESET_N: 02 - CCIMX6 Module (U1.V21), 07 - USB OTG, USB HUB, USB Host (R69.2 U13.26)
USB_OTG_D_N: 02 - CCIMX6 Module (U1.G16), 07 - USB OTG, USB HUB, USB Host (L10.1)
USB_OTG_D_P: 02 - CCIMX6 Module (U1.G17), 07 - USB OTG, USB HUB, USB Host (L10.4)
USB_OTG_ID: 02 - CCIMX6 Module (U1.K3), 07 - USB OTG, USB HUB, USB Host (J16.4 U20.1)
USB_OTG_OC: 02 - CCIMX6 Module (U1.Y16), 07 - USB OTG, USB HUB, USB Host (R64.1 U12.2)
USB_OTG_PWR: 02 - CCIMX6 Module (U1.Y18), 07 - USB OTG, USB HUB, USB Host (U12.1)
USB_OTG_VBUS: 02 - CCIMX6 Module (U1.G14), 07 - USB OTG, USB HUB, USB Host (U15.D)
USBH3_D_N: 04 - SATA, microSD, Mini PCIe, microSIM (J12.36), 07 - USB OTG, USB HUB, USB Host (L14.2)
USBH3_D_P: 04 - SATA, microSD, Mini PCIe, microSIM (J12.38), 07 - USB OTG, USB HUB, USB Host (L14.3)
USBH4_D_N: 07 - USB OTG, USB HUB, USB Host (L16.2), 10 - CAN, I2C, XBee (R129.1), 11 - Expansion Connectors, User LEDs (J32.3)
USBH4_D_P: 07 - USB OTG, USB HUB, USB Host (L16.3), 10 - CAN, I2C, XBee (R102.1), 11 - Expansion Connectors, User LEDs (J32.2)
USBH4_OC_N: 07 - USB OTG, USB HUB, USB Host (U13.21), 11 - Expansion Connectors, User LEDs (J32.4)
USBH4_PWR_EN: 07 - USB OTG, USB HUB, USB Host (U13.20), 11 - Expansion Connectors, User LEDs (J32.5)
USBH_D_N: 02 - CCIMX6 Module (U1.C16), 07 - USB OTG, USB HUB, USB Host (U13.30)
USBH_D_P: 02 - CCIMX6 Module (U1.D16), 07 - USB OTG, USB HUB, USB Host (U13.31)
USER_LED0: 02 - CCIMX6 Module (U1.G21), 11 - Expansion Connectors, User LEDs (R121.2)
USER_LED1: 02 - CCIMX6 Module (U1.G23), 11 - Expansion Connectors, User LEDs (R120.2)
USER_LED2: 02 - CCIMX6 Module (U1.K24), 11 - Expansion Connectors, User LEDs (R119.2)
XBEE_IDENT: 02 - CCIMX6 Module (U1.G24), 10 - CAN, I2C, XBee (J24.1 J25.1 R136.1)
XBEE_ON/SLEEP_N: 02 - CCIMX6 Module (U1.AD18), 10 - CAN, I2C, XBee (J24.8 Q5.G)
XBEE_RESET_N: 02 - CCIMX6 Module (U1.AB17), 10 - CAN, I2C, XBee (J23.5)
XBEE_SLEEP_RQ: 02 - CCIMX6 Module (U1.W16), 10 - CAN, I2C, XBee (J23.9 R146.2)

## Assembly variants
55001809-02: not fitted C89 C111 C114 C118 D11 J10 J11 J18 L28 Q5 R6 R24 R25 R28 R29 R39 R50 R54 R56 R59 R67 R84 R93 R101 R123 R130 R131 R133 R134 R135 R136 R137 R145 R146 R149 R150 R151 R152 R257 R258 R259
55001809-04: not fitted C14 C15 C16 C17 C89 C111 C114 C118 D11 J8 J10 J11 J17 J18 J21 J31 L28 L36 L38 L40 L42 L44 L45 Q5 R6 R24 R25 R28 R29 R39 R50 R54 R56 R59 R67 R78 R84 R93 R101 R103 R105 R108 R111 R118 R123 R130 R131 R133 R134 R135 R136 R137 R145 R146 R149 R150 R151 R152 R257 R258 R259 R298 R299
55001809-19: not fitted C14 C15 C16 C17 C31 C32 C34 C35 C36 C37 C38 C39 C40 C41 C87 C88 C89 C90 C91 C92 C93 C94 C95 C96 C97 C98 C99 C100 C102 C103 C105 C106 C107 C108 C109 C110 C111 C112 C113 C114 C115 C116 C117 C118 C119 D7 D8 D9 D11 J8 J10 J11 J12 J14 J17 J18 J19 J21 J22 J26 J27 J28 J31 J33 J34 L1 L18 L19 L20 L21 L22 L23 L24 L25 L26 L27 L29 L30 L31 L32 L33 L34 L35 L36 L38 L40 L42 L44 L45 P18 P20 Q4 Q5 R6 R24 R25 R28 R29 R39 R42 R43 R44 R47 R50 R51 R52 R54 R56 R59 R67 R76 R78 R84 R91 R92 R93 R94 R95 R96 R97 R98 R101 R102 R103 R104 R105 R106 R107 R108 R111 R112 R113 R114 R115 R116 R117 R118 R122 R123 R128 R129 R130 R131 R132 R133 R134 R135 R136 R137 R138 R139 R140 R141 R142 R143 R144 R145 R146 R149 R150 R151 R152 R155 R156 R207 R208 R257 R258 R259 R298 R299 U17 U18 U19 U22 U23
